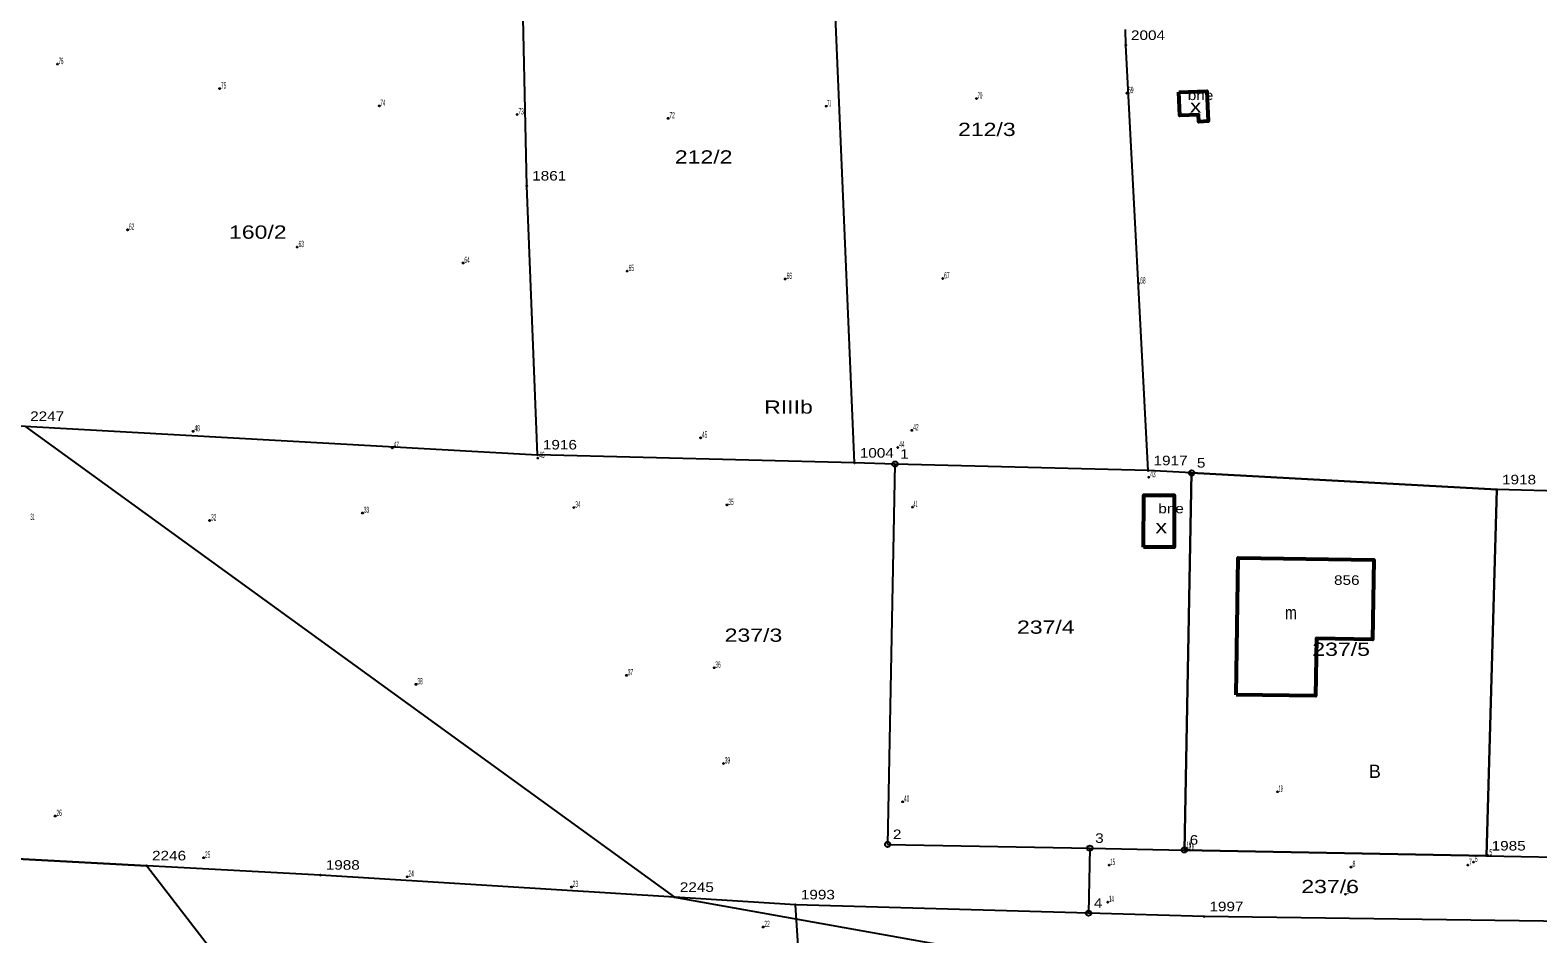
# Model space of a CAD drawing. Extents: x 4640203 to 4641683, y 5358965 to 5360242.
# Drawn here: x 4641021.5 to 4641163.8, y 5359891.2 to 5359976.5 of the extents above; entities that cross this region are included whole.
import ezdxf
from ezdxf.enums import TextEntityAlignment as Align

# ---------------------------------------------------------------- set-up
doc = ezdxf.new("R2010")
doc.units = 0
doc.header["$LTSCALE"] = 0.36
for name, color, linetype in [('24', 7, 'Continuous'), ('26', 7, 'Continuous'), ('4', 7, 'Continuous')]:
    doc.layers.add(name, color=color, linetype=linetype)
for name, color, linetype, lineweight in [('25', 7, 'Continuous', 25), ('27', 7, 'Continuous', 25), ('3', 7, 'Continuous', 53), ('63', 7, 'Continuous', 25), ('8', 7, 'Continuous', 25)]:
    doc.layers.add(name, color=color, linetype=linetype, lineweight=lineweight)

msp = doc.modelspace()

# ---------------------------------------------------------------- linework, layer by layer
at = {"layer": '25'}
for p, q in [((4641131.13, 5359934.72), (4641159.92, 5359933.14)), ((4641121.53, 5359899.32), (4641121.41, 5359893.19)), ((4641158.94, 5359898.6), (4641130.45, 5359899.15))]:
    msp.add_line(p, q, dxfattribs=at)
for points in [[(4641012.13, 5359939.61), (4641021.04, 5359939.12), (4641069.42, 5359936.43), (4641068.41, 5359961.8), (4641067.93, 5359983.4), (4641067.87, 5359985.84), (4641044.14, 5359986.98), (4641021.21, 5359992.46), (4641014.65, 5359996.97)], [(4641102.45, 5359899.68), (4641121.53, 5359899.32), (4641130.45, 5359899.15), (4641131.13, 5359934.72), (4641127.04, 5359934.94), (4641103.14, 5359935.56)], [(4641158.94, 5359898.6), (4641218.02, 5359897.47), (4641217.88, 5359913.78), (4641216.04, 5359931.65), (4641159.92, 5359933.14)]]:
    msp.add_lwpolyline(points, close=True, dxfattribs=at)
for points in [[(4641099.32, 5359935.66), (4641097.11, 5359987.43), (4641067.93, 5359983.4)], [(4641127.04, 5359934.94), (4641124.91, 5359975.06), (4641124.88, 5359976.54)], [(4641103.14, 5359935.56), (4641099.32, 5359935.66), (4641069.42, 5359936.43)], [(4641090.44, 5359814.31), (4641093.89, 5359832.35), (4641094.08, 5359835.57), (4641095.72, 5359864.07), (4641093.76, 5359893.99), (4641082.34, 5359894.7), (4641048.93, 5359896.79), (4641032.54, 5359897.67), (4641000.39, 5359899.39), (4640979.76, 5359900.7), (4640978.53, 5359871.39), (4640977.73, 5359852.38), (4640977.07, 5359836.64)], [(4641174.11, 5359771.55), (4641174.7, 5359774.3), (4641182, 5359790.6), (4641187.23, 5359798.3), (4641190.04, 5359802.44), (4641197.16, 5359815.06), (4641198.51, 5359817.46), (4641202.09, 5359826.46), (4641205.62, 5359835.77), (4641209, 5359845.63), (4641210.76, 5359850.25), (4641212.91, 5359860.38), (4641214.86, 5359870.62), (4641216.25, 5359879.44), (4641216.41, 5359880.46), (4641217.77, 5359891.85), (4641194.07, 5359892.03), (4641132.31, 5359892.87), (4641121.41, 5359893.19), (4641093.76, 5359893.99)]]:
    msp.add_lwpolyline(points, dxfattribs=at)
at = {"layer": '27'}
for points in [[(4640899.67, 5359987.05), (4640938.17, 5359945.03), (4640980.23, 5359941.38), (4641012.13, 5359939.61), (4641021.04, 5359939.12), (4641082.34, 5359894.7), (4641125.28, 5359887.02), (4641158.69, 5359881.42)], [(4640641.2, 5359946.4), (4640662.1, 5359955.08), (4640682.79, 5359959.07), (4640685.79, 5359951.97), (4640721.09, 5359953.39), (4640750.46, 5359954.58), (4640781.35, 5359955.82), (4640790.81, 5359956.61), (4640790.2, 5359946.91), (4640912.32, 5359920.03), (4640919.77, 5359924.85), (4640979.76, 5359900.7), (4641000.39, 5359899.39), (4641032.54, 5359897.67), (4641072.49, 5359845.84)]]:
    msp.add_lwpolyline(points, dxfattribs=at)
msp.add_lwpolyline([(4641130.45, 5359899.15), (4641158.94, 5359898.6), (4641159.92, 5359933.14), (4641131.13, 5359934.72)], close=True, dxfattribs=at)
at = {"layer": '3'}
for points in [[(4641129.94, 5359970.62), (4641132.56, 5359970.73), (4641132.69, 5359967.89), (4641131.8, 5359967.85), (4641131.77, 5359968.5), (4641130.03, 5359968.43)], [(4641126.6, 5359927.72), (4641126.61, 5359932.62), (4641129.5, 5359932.61), (4641129.49, 5359927.71)], [(4641135.33, 5359913.8), (4641135.51, 5359926.7), (4641148.31, 5359926.52), (4641148.2, 5359919.02), (4641142.91, 5359919.1), (4641142.83, 5359913.7)]]:
    msp.add_lwpolyline(points, close=True, dxfattribs=at)
at = {"layer": '63'}
for centre in [(4641024.12, 5359973.28), (4641024.12, 5359973.28), (4641039.42, 5359970.97), (4641039.42, 5359970.97), (4641110.83, 5359970.03), (4641110.83, 5359970.03), (4641125.02, 5359970.54), (4641125.02, 5359970.54), (4641054.49, 5359969.34), (4641054.49, 5359969.34), (4641067.49, 5359968.53), (4641067.49, 5359968.53), (4641081.74, 5359968.17), (4641081.74, 5359968.17), (4641096.64, 5359969.31), (4641096.64, 5359969.31), (4641030.74, 5359957.65), (4641030.74, 5359957.65), (4641046.74, 5359956.02), (4641046.74, 5359956.02), (4641062.39, 5359954.52), (4641062.39, 5359954.52), (4641077.88, 5359953.76), (4641077.88, 5359953.76), (4641092.79, 5359953.01), (4641092.79, 5359953.01), (4641107.66, 5359953.06), (4641107.66, 5359953.06), (4641126.16, 5359952.58), (4641126.16, 5359952.58), (4641036.92, 5359938.64), (4641036.92, 5359938.64), (4641104.74, 5359938.74), (4641104.74, 5359938.74), (4641055.71, 5359937.08), (4641055.71, 5359937.08), (4641084.81, 5359938.03), (4641084.81, 5359938.03), (4641103.42, 5359937.12), (4641103.42, 5359937.12), (4641069.45, 5359936.12), (4641069.45, 5359936.12), (4641127.1, 5359934.31), (4641127.1, 5359934.31), (4641072.85, 5359931.45), (4641072.85, 5359931.45), (4641087.29, 5359931.7), (4641087.29, 5359931.7), (4641104.79, 5359931.5), (4641104.79, 5359931.5), (4641038.48, 5359930.23), (4641038.48, 5359930.23), (4641052.9, 5359930.94), (4641052.9, 5359930.94), (4641077.81, 5359915.63), (4641077.81, 5359915.63), (4641086.07, 5359916.34), (4641086.07, 5359916.34), (4641057.95, 5359914.78), (4641057.95, 5359914.78), (4641086.96, 5359907.31), (4641086.96, 5359907.31), (4641139.24, 5359904.64), (4641139.24, 5359904.64), (4641103.87, 5359903.7), (4641103.87, 5359903.7), (4641023.9, 5359902.36), (4641023.9, 5359902.36), (4641037.91, 5359898.42), (4641037.91, 5359898.42), (4641130.54, 5359899.18), (4641130.54, 5359899.18), (4641130.56, 5359899.34), (4641130.56, 5359899.34), (4641130.82, 5359899.15), (4641130.82, 5359899.15), (4641159.09, 5359898.64), (4641159.09, 5359898.64), (4641123.35, 5359897.73), (4641123.35, 5359897.73), (4641146.17, 5359897.54), (4641146.17, 5359897.54), (4641157.19, 5359897.73), (4641157.19, 5359897.73), (4641157.74, 5359898.01), (4641157.74, 5359898.01), (4641057.11, 5359896.63), (4641057.11, 5359896.63), (4641072.61, 5359895.66), (4641072.61, 5359895.66), (4641123.23, 5359894.23), (4641123.23, 5359894.23), (4641145.66, 5359894.98), (4641145.66, 5359894.98), (4641090.7, 5359891.89), (4641090.7, 5359891.89)]:
    msp.add_circle(centre, 0.05, dxfattribs=at)
at = {"layer": '8'}
for centre, radius in [((4641124.91, 5359975.06), 0.045), ((4641068.41, 5359961.8), 0.045), ((4641069.42, 5359936.43), 0.045), ((4641099.32, 5359935.66), 0.045), ((4641103.14, 5359935.56), 0.25), ((4641127.04, 5359934.94), 0.045), ((4641131.13, 5359934.72), 0.25), ((4641159.92, 5359933.14), 0.045), ((4641102.45, 5359899.68), 0.25), ((4641121.53, 5359899.32), 0.25), ((4641130.45, 5359899.15), 0.25), ((4641158.94, 5359898.6), 0.045), ((4641032.54, 5359897.67), 0.045), ((4641048.93, 5359896.79), 0.045), ((4641082.34, 5359894.7), 0.045), ((4641093.76, 5359893.99), 0.045), ((4641121.41, 5359893.19), 0.25), ((4641132.31, 5359892.87), 0.045)]:
    msp.add_circle(centre, radius, dxfattribs=at)

# ---------------------------------------------------------------- texts
at = {"layer": '24', "width": 1.3}
for s, p in [('212/3', (4641109.09, 5359966.5)), ('212/2', (4641082.37, 5359963.9)), ('160/2', (4641040.3, 5359956.81)), ('237/3', (4641087.07, 5359918.79)), ('237/4', (4641114.65, 5359919.55)), ('237/5', (4641142.52, 5359917.46)), ('237/6', (4641141.48, 5359895.08))]:
    msp.add_text(s, height=1.25, dxfattribs=at).set_placement(p)
at = {"layer": '26', "width": 1.3}
msp.add_text('RIIIb', height=1.25, dxfattribs=at).set_placement((4641090.8, 5359940.31))
at = {"layer": '26'}
msp.add_text('B', height=1.25, dxfattribs=at).set_placement((4641147.87, 5359905.95))
at = {"layer": '4', "width": 1.2}
for s, p in [('bne', (4641130.77, 5359969.89)), ('bne', (4641127.99, 5359930.91)), ('856', (4641144.57, 5359924.16))]:
    msp.add_text(s, height=0.9, dxfattribs=at).set_placement(p)
at = {"layer": '4'}
for s, width, p in [('x', 1.3, (4641131.51, 5359968.7)), ('x', 1.3, (4641128.27, 5359929.03)), ('m', 0.8, (4641140.5, 5359920.92))]:
    msp.add_text(s, height=1.25, dxfattribs=dict(at, width=width)).set_placement(p, align=Align.CENTER)
at = {"layer": '63'}
for s, width, p in [(' 76', 0.4, (4641024.12, 5359973.28)), (' 76', 0.4, (4641024.12, 5359973.28)), (' 75', 0.45, (4641039.42, 5359970.97)), (' 75', 0.45, (4641039.42, 5359970.97)), (' 69', 0.45, (4641125.02, 5359970.54)), (' 69', 0.45, (4641125.02, 5359970.54)), (' 74', 0.4, (4641054.49, 5359969.34)), (' 74', 0.4, (4641054.49, 5359969.34)), (' 71', 0.35, (4641096.64, 5359969.31)), (' 71', 0.35, (4641096.64, 5359969.31)), (' 70', 0.4, (4641110.83, 5359970.03)), (' 70', 0.4, (4641110.83, 5359970.03)), (' 73', 0.45, (4641067.49, 5359968.53)), (' 73', 0.45, (4641067.49, 5359968.53)), (' 72', 0.45, (4641081.74, 5359968.17)), (' 72', 0.45, (4641081.74, 5359968.17)), (' 62', 0.45, (4641030.74, 5359957.65)), (' 62', 0.45, (4641030.74, 5359957.65)), (' 63', 0.45, (4641046.74, 5359956.02)), (' 63', 0.45, (4641046.74, 5359956.02)), (' 64', 0.45, (4641062.39, 5359954.52)), (' 64', 0.45, (4641062.39, 5359954.52)), (' 65', 0.45, (4641077.88, 5359953.76)), (' 65', 0.45, (4641077.88, 5359953.76)), (' 66', 0.45, (4641092.79, 5359953.01)), (' 66', 0.45, (4641092.79, 5359953.01)), (' 67', 0.45, (4641107.66, 5359953.06)), (' 67', 0.45, (4641107.66, 5359953.06)), (' 68', 0.45, (4641126.16, 5359952.58)), (' 68', 0.45, (4641126.16, 5359952.58)), (' 48', 0.45, (4641036.92, 5359938.64)), (' 48', 0.45, (4641036.92, 5359938.64)), (' 45', 0.45, (4641084.81, 5359938.03)), (' 45', 0.45, (4641084.81, 5359938.03)), (' 42', 0.45, (4641104.74, 5359938.74)), (' 42', 0.45, (4641104.74, 5359938.74)), (' 47', 0.45, (4641055.71, 5359937.08)), (' 47', 0.45, (4641055.71, 5359937.08)), (' 46', 0.45, (4641069.45, 5359936.12)), (' 46', 0.45, (4641069.45, 5359936.12)), (' 44', 0.45, (4641103.42, 5359937.12)), (' 44', 0.45, (4641103.42, 5359937.12)), (' 43', 0.45, (4641127.1, 5359934.31)), (' 43', 0.45, (4641127.1, 5359934.31)), (' 33', 0.45, (4641052.9, 5359930.94)), (' 33', 0.45, (4641052.9, 5359930.94)), (' 34', 0.45, (4641072.85, 5359931.45)), (' 34', 0.45, (4641072.85, 5359931.45)), (' 35', 0.45, (4641087.29, 5359931.7)), (' 35', 0.45, (4641087.29, 5359931.7)), (' 41', 0.35, (4641104.79, 5359931.5)), (' 41', 0.35, (4641104.79, 5359931.5)), (' 31', 0.35, (4641021.47, 5359930.28)), (' 31', 0.35, (4641021.47, 5359930.28)), (' 32', 0.45, (4641038.48, 5359930.23)), (' 32', 0.45, (4641038.48, 5359930.23)), (' 36', 0.45, (4641086.07, 5359916.34)), (' 36', 0.45, (4641086.07, 5359916.34)), (' 38', 0.45, (4641057.95, 5359914.78)), (' 38', 0.45, (4641057.95, 5359914.78)), (' 37', 0.45, (4641077.81, 5359915.63)), (' 37', 0.45, (4641077.81, 5359915.63)), (' 39', 0.45, (4641086.96, 5359907.31)), (' 39', 0.45, (4641086.96, 5359907.31)), (' 40', 0.45, (4641103.87, 5359903.7)), (' 40', 0.45, (4641103.87, 5359903.7)), (' 19', 0.35, (4641139.24, 5359904.64)), (' 19', 0.35, (4641139.24, 5359904.64)), (' 26', 0.45, (4641023.9, 5359902.36)), (' 26', 0.45, (4641023.9, 5359902.36)), (' 17', 0.4, (4641130.54, 5359899.18)), (' 17', 0.4, (4641130.54, 5359899.18)), (' 16', 0.35, (4641130.56, 5359899.34)), (' 16', 0.35, (4641130.56, 5359899.34)), (' 18', 0.4, (4641130.82, 5359899.15)), (' 18', 0.4, (4641130.82, 5359899.15)), (' 25', 0.45, (4641037.91, 5359898.42)), (' 25', 0.45, (4641037.91, 5359898.42)), (' 15', 0.4, (4641123.35, 5359897.73)), (' 15', 0.4, (4641123.35, 5359897.73)), (' 7', 0.45, (4641157.19, 5359897.73)), (' 7', 0.45, (4641157.19, 5359897.73)), (' 6', 0.45, (4641157.74, 5359898.01)), (' 6', 0.45, (4641157.74, 5359898.01)), (' 5', 0.5, (4641159.09, 5359898.64)), (' 5', 0.5, (4641159.09, 5359898.64)), (' 24', 0.45, (4641057.11, 5359896.63)), (' 24', 0.45, (4641057.11, 5359896.63)), (' 8', 0.5, (4641146.17, 5359897.54)), (' 8', 0.5, (4641146.17, 5359897.54)), (' 23', 0.45, (4641072.61, 5359895.66)), (' 23', 0.45, (4641072.61, 5359895.66)), (' 9', 0.45, (4641145.66, 5359894.98)), (' 9', 0.45, (4641145.66, 5359894.98)), (' 14', 0.4, (4641123.23, 5359894.23)), (' 14', 0.4, (4641123.23, 5359894.23)), (' 22', 0.45, (4641090.7, 5359891.89)), (' 22', 0.45, (4641090.7, 5359891.89))]:
    msp.add_text(s, height=0.6, dxfattribs=dict(at, width=width)).set_placement(p)
at = {"layer": '8', "width": 1.2}
for s, p in [('2004', (4641125.41, 5359975.56)), ('1861', (4641068.91, 5359962.3)), ('2247', (4641021.54, 5359939.62)), ('1916', (4641069.92, 5359936.93)), ('1004', (4641099.82, 5359936.16)), ('1', (4641103.64, 5359936.06)), ('1917', (4641127.54, 5359935.44)), ('5', (4641131.63, 5359935.22)), ('1918', (4641160.42, 5359933.64)), ('2', (4641102.95, 5359900.18)), ('3', (4641122.03, 5359899.82)), ('6', (4641130.95, 5359899.65)), ('1985', (4641159.44, 5359899.1)), ('2246', (4641033.04, 5359898.17)), ('1988', (4641049.43, 5359897.29)), ('2245', (4641082.84, 5359895.2)), ('1993', (4641094.26, 5359894.49)), ('4', (4641121.91, 5359893.69)), ('1997', (4641132.81, 5359893.37))]:
    msp.add_text(s, height=0.9, dxfattribs=at).set_placement(p)

doc.saveas('drawing.dxf')
